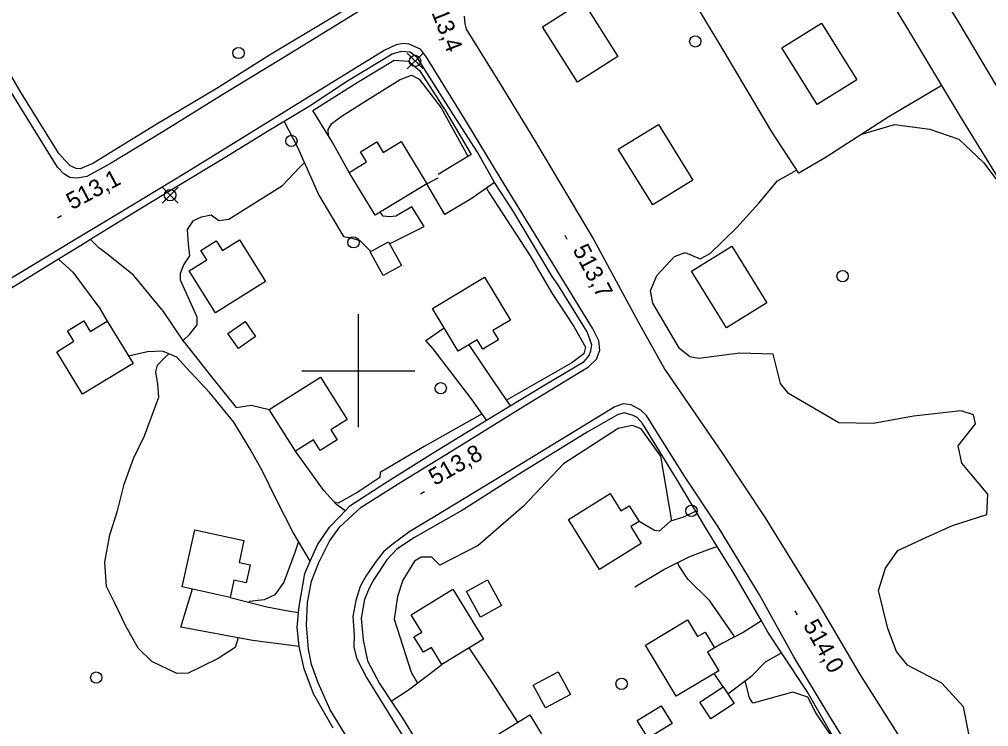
# Model space of a CAD drawing. Extents: x 347312 to 350503, y 6073086 to 6076432.
# Drawn here: x 348840.1 to 349011.5, y 6075337 to 6075462.2 of the extents above; entities that cross this region are included whole.
import ezdxf

# ---------------------------------------------------------------- set-up
doc = ezdxf.new("R2010")
doc.units = 0
for name, color, linetype in [('Level 19', 7, 'Continuous'), ('Level 2', 7, 'Continuous'), ('Level 21', 7, 'Continuous'), ('Level 22', 7, 'Continuous'), ('Level 3', 7, 'Continuous'), ('Level 31', 7, 'Continuous'), ('Level 36', 7, 'Continuous'), ('Level 37', 7, 'Continuous'), ('Level 61', 7, 'Continuous')]:
    doc.layers.add(name, color=color, linetype=linetype)

msp = doc.modelspace()

# ---------------------------------------------------------------- linework, layer by layer
at = {"layer": 'Level 19'}
for points in [[(349003.26, 6075450.49), (348993.76, 6075444.88), (348982.81, 6075437.77), (348977.94, 6075434.93), (348973.18, 6075442.26), (348964.77, 6075456.49), (348957.78, 6075468.12), (348952.72, 6075476.71), (348950.22, 6075480.8), (348948.53, 6075483.56)], [(348886.9, 6075444.08), (348889.25, 6075439.57), (348893.03, 6075431.06), (348897.37, 6075423.77), (348898.46, 6075423.55), (348900.31, 6075423.05), (348902.21, 6075421.09)], [(348924.13, 6075433.27), (348919.96, 6075430.4), (348915.35, 6075427.63), (348912.15, 6075433.07), (348914.14, 6075434.12)], [(348905.55, 6075422.44), (348911.64, 6075425.53), (348909.49, 6075429.01), (348906.66, 6075427.35), (348905.62, 6075427.24), (348904.41, 6075427.33), (348903.86, 6075428.03)], [(348869.2, 6075405.07), (348865.55, 6075410.45), (348860.26, 6075416.88), (348855.74, 6075420.5), (348854.12, 6075421.72), (348852.64, 6075423.2)], [(348846.99, 6075419.72), (348849.53, 6075417.42), (348854.28, 6075410.99), (348855.59, 6075408.74)], [(348922.7, 6075391.26), (348920.16, 6075394.86), (348916.48, 6075399.63), (348913.25, 6075403.86), (348911.99, 6075405.37), (348915.23, 6075407.59)], [(348869.2, 6075405.07), (348874.28, 6075398.61), (348878.42, 6075393.47), (348881.09, 6075393.88), (348884.24, 6075393.13)], [(348919.56, 6075404.58), (348922.09, 6075400.82), (348926.87, 6075393.8)], [(348891.5, 6075366.32), (348888.51, 6075371.36), (348885.44, 6075377.38), (348883.09, 6075382.2), (348880.9, 6075386.09), (348877.97, 6075390.87), (348873.76, 6075396.1), (348869.57, 6075400.59), (348867.92, 6075402.38), (348865.39, 6075403.43), (348862.75, 6075403.35), (348859.36, 6075402.56)], [(348897.67, 6075375.19), (348896.13, 6075376.32), (348893.89, 6075378.83), (348888.88, 6075385.76)], [(348959.71, 6075375.16), (348957.55, 6075374.06), (348955.27, 6075373.37), (348953.25, 6075371.62), (348952.4, 6075371.74), (348949.68, 6075373.32)], [(348948.94, 6075361.76), (348954.08, 6075364.81), (348958.66, 6075367.1), (348962.08, 6075368.42), (348963.5, 6075368.91)], [(348889.56, 6075351.19), (348881.27, 6075352.29), (348868.64, 6075354.61), (348870.68, 6075361.38)], [(348877.32, 6075359.9), (348883.83, 6075358.23), (348887.23, 6075357.59), (348889.46, 6075357.22)], [(348971.33, 6075355.75), (348968.09, 6075353.67), (348964.54, 6075351.87), (348962.75, 6075350.79)], [(348928.25, 6075337.8), (348923.64, 6075344.96), (348919.66, 6075350.97)], [(348965.39, 6075342.8), (348969.69, 6075346.06), (348972.05, 6075348.47), (348974.91, 6075350.08)], [(348905.86, 6075341.52), (348908.92, 6075343.53), (348912.47, 6075346.24), (348914.82, 6075348.01)], [(348964.54, 6075344.08), (348962.98, 6075346.44)]]:
    msp.add_lwpolyline(points, dxfattribs=at)
at = {"layer": 'Level 2'}
for points in [[(348896.98, 6075444.97), (348901.63, 6075447.91), (348907.42, 6075451.54), (348909.42, 6075452.29), (348910.79, 6075451.57), (348914.7, 6075446.5), (348919.39, 6075437.93)], [(348894.77, 6075441.49), (348894.69, 6075442.66), (348895.36, 6075443.75), (348896.98, 6075444.97)], [(348989.12, 6075441.86), (348994.87, 6075443.56), (349001.14, 6075442.74), (349006.29, 6075440.99), (349010.61, 6075436.82), (349014.84, 6075431.3), (349021.96, 6075419.24), (349024.3, 6075415.53)], [(348869.03, 6075405.33), (348870.17, 6075406.38), (348871.48, 6075408.13), (348871.53, 6075409.5), (348868.54, 6075416), (348868.58, 6075417.23), (348869.15, 6075418.76), (348870.23, 6075420.32), (348869.99, 6075422.37), (348869.8, 6075424.99), (348870.87, 6075426.55), (348872.3, 6075427.2), (348873.98, 6075427.55), (348875.33, 6075426.55), (348877.09, 6075426.79), (348886.58, 6075432.74), (348889.54, 6075435.87), (348890.47, 6075436.82)], [(349008.85, 6075331.54), (349007.09, 6075340.53), (349003.27, 6075344.74), (348997.18, 6075347.89), (348995.25, 6075350.29), (348993.7, 6075354.41), (348992.05, 6075361.09), (348993.28, 6075365.04), (348995.5, 6075368.16), (349000.41, 6075370.5), (349005.14, 6075372.61), (349011.21, 6075374.55), (349011.42, 6075378.18), (349006.78, 6075383.66), (349006.15, 6075386.68), (349009.19, 6075390.62), (349008.88, 6075392.17), (349006.68, 6075392.91), (348998.27, 6075391.96), (348991.15, 6075390.65), (348985.06, 6075390.8), (348976.15, 6075395.97), (348974.7, 6075397.71), (348973.42, 6075402.95), (348967.54, 6075403.13), (348960.29, 6075402.15), (348958.67, 6075402.47), (348956.87, 6075403.91), (348952.13, 6075411.93), (348951.72, 6075414.15), (348952.84, 6075416.87), (348955.94, 6075420.2), (348957.82, 6075420.93), (348960.52, 6075419.78), (348962.29, 6075420.72), (348966.96, 6075425.34), (348970.9, 6075429.65), (348974.18, 6075433.57), (348977.56, 6075435.51)], [(348922.67, 6075432.27), (348923.14, 6075431.47), (348930.45, 6075420.35), (348934.22, 6075413.85), (348938.12, 6075407.84), (348940.22, 6075404.17), (348939.89, 6075402.97), (348937.81, 6075401.37), (348926.22, 6075394.76)], [(348858.89, 6075354.77), (348856.97, 6075358.86), (348855.44, 6075361.83), (348855.19, 6075366.11), (348856.06, 6075370.95), (348857.39, 6075375.23), (348858.62, 6075379.95), (348860.26, 6075384.49), (348862.2, 6075388.5), (348864.7, 6075395.34), (348864.55, 6075397.6), (348864.18, 6075399.8), (348864.5, 6075401), (348865.7, 6075402.26), (348866.48, 6075402.98)], [(348921.94, 6075392.34), (348911.64, 6075386.56), (348903.9, 6075381.96), (348903.82, 6075381.1), (348899.92, 6075378.51), (348896.44, 6075376.54), (348895.76, 6075376.73)], [(348955.47, 6075373.43), (348953.55, 6075384.85), (348950.08, 6075389.72), (348948.53, 6075390.32), (348945.97, 6075389.78), (348936.34, 6075383.53), (348929.26, 6075376.02), (348921.21, 6075369.05), (348914.46, 6075365.57), (348913.03, 6075367.01), (348911.14, 6075367.03), (348909.96, 6075366.27), (348907.92, 6075362.93), (348906.95, 6075360.03), (348906.38, 6075356.02), (348909.34, 6075346.68), (348910.49, 6075344.73)], [(348889.44, 6075369.78), (348888.81, 6075367.81), (348886.83, 6075362.58), (348885.26, 6075360.34), (348883.38, 6075359.44), (348880.74, 6075359.15), (348880.7, 6075359.03)], [(348966.5, 6075352.86), (348966.43, 6075353.13), (348962.22, 6075359.26), (348958.33, 6075363.11), (348956.75, 6075365.55), (348956.57, 6075366.06)], [(348878.76, 6075352.75), (348878.22, 6075351), (348875.25, 6075349.09), (348869.91, 6075346.49), (348867.89, 6075346.4), (348863.49, 6075348.55), (348861.05, 6075350.88), (348858.89, 6075354.77)], [(348986.68, 6075330.96), (348980.99, 6075339.46), (348979.56, 6075342.26), (348976.88, 6075343.13), (348969.82, 6075341.2), (348969.21, 6075342.11), (348968.45, 6075345.12)]]:
    msp.add_lwpolyline(points, dxfattribs=at)
at = {"layer": 'Level 21'}
for points in [[(348981.68, 6075502.11), (348989.28, 6075488.94), (348998.03, 6075474.76), (348999.46, 6075472.47), (349006.1, 6075461.83), (349014.24, 6075448.19)], [(349015.65, 6075430.24), (349006.76, 6075444.68), (349003.26, 6075450.49), (348997.58, 6075459.92), (348988.44, 6075475.13)], [(348901.69, 6075464.54), (348887.33, 6075455.72), (348875.86, 6075448.78), (348865.46, 6075442.27), (348856.18, 6075436.68), (348852.01, 6075434.36), (348850.3, 6075434.07), (348848.99, 6075434.19), (348847.94, 6075434.82), (348846.81, 6075435.99), (348841.45, 6075444.69), (348836.72, 6075452.34), (348828.46, 6075466.15)], [(348918.72, 6075462.7), (348918.85, 6075461.46), (348919.09, 6075460.45), (348925, 6075450.92), (348931.37, 6075440.49), (348941.67, 6075423.17), (348949.55, 6075408.65), (348954.25, 6075400.22), (348964.31, 6075385.54), (348971.97, 6075373.99), (348981.55, 6075358.54), (348988.67, 6075346.38), (348996.84, 6075333.51), (349001.76, 6075325.44), (349002.6, 6075324.07), (349011.14, 6075310.21), (349018.66, 6075297.93)], [(348896.77, 6075372.35), (348900.5, 6075375.83), (348907.55, 6075380.3), (348917.93, 6075386.65), (348929.12, 6075393.58), (348940.77, 6075400.67), (348942.13, 6075402.02), (348942.73, 6075403.65), (348942.55, 6075405.3), (348941.44, 6075407.54), (348935.25, 6075417.59), (348931.82, 6075423.24), (348925.11, 6075434.18), (348919.19, 6075443.89), (348912.11, 6075455.46), (348911, 6075456.87), (348909.03, 6075457.79), (348907.97, 6075457.89), (348906.71, 6075457.68), (348904.61, 6075456.68), (348892.12, 6075448.97), (348881.16, 6075442.22), (348869.63, 6075435.08), (348856.95, 6075427.43), (348849.58, 6075422.98), (348835.5, 6075414.47)], [(348994.34, 6075321.24), (348983.44, 6075338.84), (348977.07, 6075349.37), (348971, 6075360.36), (348963.71, 6075372.36), (348957.74, 6075381.33), (348952.67, 6075389.39), (348950.98, 6075392.05), (348950, 6075393.04), (348948.32, 6075393.98), (348946.85, 6075394.11), (348945.4, 6075393.59), (348936.59, 6075388.25), (348925.72, 6075381.58), (348913.55, 6075374.21), (348909.14, 6075371.54), (348905.96, 6075369.2), (348904.45, 6075367.95), (348903.18, 6075366.3), (348901.33, 6075363.64), (348900.34, 6075361.84), (348899.57, 6075359.33), (348899.06, 6075356.5), (348899.26, 6075353.28), (348899.22, 6075351.07), (348899.73, 6075349.01), (348901.44, 6075345.69), (348906.82, 6075337.06), (348911.74, 6075329.26)], [(348900.56, 6075331), (348895.01, 6075340.01), (348892.9, 6075344.8), (348891.72, 6075348.03), (348891.22, 6075350.7), (348890.83, 6075354.97), (348891.04, 6075358.97), (348891.72, 6075362.77), (348893.02, 6075366.09), (348894.93, 6075369.86), (348896.77, 6075372.35)]]:
    msp.add_lwpolyline(points, dxfattribs=at)
at = {"layer": 'Level 22'}
for points in [[(348901.69, 6075464.54), (348900.87, 6075465.84), (348895.33, 6075462.45), (348884.32, 6075455.81), (348874.88, 6075449.87), (348864.55, 6075443.73), (348853.03, 6075436.67), (348850.81, 6075435.72), (348850.11, 6075435.75), (348849.01, 6075436.26), (348848.15, 6075437.2), (348847.06, 6075438.41), (348840.37, 6075449.16), (348834.18, 6075459.65), (348826.97, 6075471.1), (348820.1, 6075482.15), (348819.03, 6075481.41)], [(348941.35, 6075404.59), (348940.5, 6075406.89), (348935.34, 6075415.24), (348934.32, 6075416.65), (348927.37, 6075428.33), (348924.13, 6075433.27), (348921.08, 6075438.64), (348916.77, 6075445.44), (348910.41, 6075455.42), (348909.18, 6075456.35), (348907.62, 6075456.49), (348906.01, 6075455.98), (348898.08, 6075451.22), (348891.33, 6075446.75), (348886.9, 6075444.08), (348883.96, 6075442.3), (348875.84, 6075437.31), (348867.95, 6075432.58), (348859.23, 6075427.31), (348852.64, 6075423.2), (348850.85, 6075422.09), (348846.99, 6075419.72), (348837.89, 6075414.14)], [(348895.56, 6075336.76), (348892.08, 6075342.83), (348890.43, 6075347.25), (348889.56, 6075351.19), (348889.22, 6075354.59), (348889.46, 6075357.22), (348889.56, 6075358.25), (348890.55, 6075364.11), (348891.5, 6075366.32), (348892.79, 6075369.2), (348894.93, 6075372.32), (348896.8, 6075374.24), (348897.67, 6075375.19), (348898.49, 6075376.1), (348904.71, 6075380.12), (348913.28, 6075385.48), (348922.7, 6075391.26), (348926.87, 6075393.8), (348932.7, 6075397.35), (348939.97, 6075401.64), (348940.89, 6075402.71), (348941.18, 6075403.54), (348941.35, 6075404.59)], [(348983.84, 6075335.52), (348979.44, 6075343.23), (348974.91, 6075350.08), (348972.5, 6075353.73), (348971.33, 6075355.75), (348966.53, 6075364.05), (348963.5, 6075368.91), (348961.43, 6075372.24), (348959.71, 6075375.16), (348956.34, 6075380.88), (348950.32, 6075390.63), (348949.35, 6075391.7), (348948.65, 6075392.09), (348947.04, 6075392.57), (348945.85, 6075392.19), (348940.5, 6075389.11), (348928.36, 6075381.62), (348918.44, 6075375.35), (348909.87, 6075370.44), (348906.8, 6075368.34), (348905.06, 6075366.53), (348902.77, 6075363.05), (348901.93, 6075361.53), (348901.12, 6075359.51), (348900.53, 6075356.24), (348900.87, 6075352.39), (348901.64, 6075348.67), (348903.78, 6075344.65), (348905.86, 6075341.52), (348907.83, 6075338.53), (348911.84, 6075332)]]:
    msp.add_lwpolyline(points, dxfattribs=at)
at = {"layer": 'Level 3'}
for p, q in [((348846.82, 6075427.07), (348847.52, 6075427.45)), ((348936.56, 6075423.98), (348936.93, 6075423.28)), ((348911.01, 6075378.21), (348911.71, 6075378.6)), ((348977.26, 6075357.5), (348977.65, 6075356.8))]:
    msp.add_line(p, q, dxfattribs=at)
at = {"layer": 'Level 31'}
for points in [[(348938.8, 6075451.08), (348932.6, 6075460.84), (348939.75, 6075465.38), (348945.95, 6075455.61), (348938.8, 6075451.08)], [(348981.19, 6075447.09), (348974.94, 6075457.11), (348981.95, 6075461.49), (348988.2, 6075451.47), (348981.19, 6075447.09)], [(348952.13, 6075429.33), (348946.02, 6075439.17), (348953.11, 6075443.56), (348959.21, 6075433.72), (348952.13, 6075429.33)], [(348912.15, 6075433.07), (348902.99, 6075427.5), (348898.39, 6075435.07), (348901.47, 6075436.94), (348900.39, 6075438.72), (348903.27, 6075440.47), (348904.39, 6075438.63), (348907.59, 6075440.58), (348912.15, 6075433.07)], [(348883.61, 6075415.8), (348874.74, 6075410.24), (348870.09, 6075417.67), (348873.22, 6075419.63), (348872.18, 6075421.29), (348874.89, 6075422.99), (348875.99, 6075421.24), (348879.02, 6075423.14), (348883.61, 6075415.8)], [(348904.39, 6075416.86), (348902.1, 6075421.04), (348905.35, 6075422.81), (348907.63, 6075418.63), (348904.39, 6075416.86)], [(348965.15, 6075407.6), (348958.97, 6075417.62), (348966.13, 6075422.03), (348972.31, 6075412.01), (348965.15, 6075407.6)], [(348915.23, 6075407.59), (348913.17, 6075411.02), (348922.37, 6075416.55), (348926.92, 6075408.97), (348923.82, 6075407.11), (348924.81, 6075405.45), (348922.05, 6075403.79), (348921.04, 6075405.47), (348917.7, 6075403.46), (348913.17, 6075411.02)], [(348855.59, 6075408.74), (348860.16, 6075401.25), (348851.25, 6075395.82), (348846.66, 6075403.36), (348849.71, 6075405.22), (348848.58, 6075407.08), (348851.43, 6075408.81), (348852.59, 6075406.91), (348855.59, 6075408.74)], [(348876.95, 6075406.58), (348879.98, 6075408.71), (348881.85, 6075406.06), (348878.82, 6075403.93), (348876.95, 6075406.58)], [(348884.24, 6075393.13), (348893.3, 6075398.84), (348898.02, 6075391.34), (348895.15, 6075389.54), (348896.28, 6075387.74), (348893.29, 6075385.86), (348892.08, 6075387.78), (348888.88, 6075385.76), (348884.24, 6075393.13)], [(348942.7, 6075364.84), (348937.2, 6075373.69), (348944.55, 6075378.25), (348946.46, 6075375.18), (348947.95, 6075376.1), (348949.68, 6075373.32), (348948.22, 6075372.41), (348950.08, 6075369.42), (348942.7, 6075364.84)], [(348868.88, 6075361.78), (348871.12, 6075371.87), (348879.79, 6075369.94), (348878.93, 6075366.08), (348880.86, 6075365.65), (348880.16, 6075362.49), (348878, 6075362.96), (348877.32, 6075359.9), (348868.88, 6075361.78)], [(348921.64, 6075356.4), (348919.15, 6075360.93), (348922.87, 6075362.99), (348925.36, 6075358.46), (348921.64, 6075356.4)], [(348916.77, 6075361.37), (348922.19, 6075352.52), (348914.82, 6075348.01), (348912.95, 6075351.05), (348911.53, 6075350.18), (348909.86, 6075352.91), (348911.23, 6075353.74), (348909.34, 6075356.82), (348916.77, 6075361.37)], [(348956.26, 6075342.4), (348950.82, 6075351.45), (348958.26, 6075355.93), (348960.05, 6075352.95), (348961.36, 6075353.74), (348963.03, 6075350.96), (348961.8, 6075350.22), (348963.78, 6075346.92), (348956.26, 6075342.4)], [(348937.55, 6075342.73), (348933.14, 6075340.36), (348930.98, 6075344.36), (348935.39, 6075346.74), (348937.55, 6075342.73)], [(348960.43, 6075341.35), (348964.54, 6075344.08), (348966.51, 6075341.11), (348962.4, 6075338.38), (348960.43, 6075341.35)], [(348955.52, 6075337.59), (348951.3, 6075334.99), (348949.38, 6075338.11), (348953.6, 6075340.71), (348955.52, 6075337.59)], [(348930.37, 6075339.09), (348935.79, 6075330.17), (348928.3, 6075325.63), (348926.41, 6075328.75), (348925.01, 6075327.9), (348923.34, 6075330.65), (348924.7, 6075331.48), (348922.85, 6075334.53), (348930.37, 6075339.09)]]:
    msp.add_lwpolyline(points, dxfattribs=at)
at = {"layer": 'Level 36'}
for p, q in [((348908.65, 6075453.39), (348911.47, 6075456.21)), ((348908.65, 6075456.21), (348911.47, 6075453.39)), ((348865.32, 6075429.65), (348868.14, 6075432.47)), ((348865.32, 6075432.47), (348868.14, 6075429.65))]:
    msp.add_line(p, q, dxfattribs=at)
for centre in [(348959.64, 6075458.26), (348878.82, 6075456.21), (348910.06, 6075454.8), (348888.19, 6075440.66), (348866.73, 6075431.06), (348899.16, 6075422.71), (348985.7, 6075416.73), (348914.6, 6075396.9), (348958.97, 6075375.21), (348853.66, 6075345.7), (348946.59, 6075344.6)]:
    msp.add_circle(centre, 1, dxfattribs=at)
at = {"layer": 'Level 37'}
msp.add_lwpolyline([(348898.72, 6075434.53), (348895.39, 6075440.48), (348891.96, 6075446.04), (348899.81, 6075451), (348906.38, 6075454.95), (348908.87, 6075454.76), (348910.86, 6075453.1), (348915.43, 6075446), (348919.98, 6075438.28), (348914.14, 6075434.72)], dxfattribs=at)
at = {"layer": 'Level 61'}
for p, q in [((348900, 6075410), (348900, 6075390)), ((348890, 6075400), (348910, 6075400))]:
    msp.add_line(p, q, dxfattribs=at)

# ---------------------------------------------------------------- texts
at = {"layer": 'Level 3'}
for s, rotation, p in [('513,4', 291.3704, (348912.12, 6075465.43)), ('513,1', 28.0171, (348849.37, 6075428.4)), ('513,7', 297.6928, (348937.87, 6075421.42)), ('513,8', 29.4061, (348913.54, 6075379.59)), ('514,0', 299.1381, (348978.63, 6075354.97))]:
    msp.add_text(s, height=3, rotation=rotation, dxfattribs=at).set_placement(p)

doc.saveas('drawing.dxf')
